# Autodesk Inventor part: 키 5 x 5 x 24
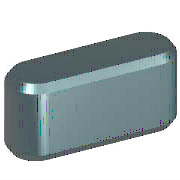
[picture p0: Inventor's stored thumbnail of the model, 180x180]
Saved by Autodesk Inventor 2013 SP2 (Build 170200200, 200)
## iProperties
IsCustomPart: 1
Created: 2012-02
Part Number: 키 5 x 5 x 24
Material: 강철, 연강
Description: 키 및 해당 키홈
Document SubType Name: Modeling
Standard: KS B 1311
Designer: mduedu
Standards Organization: KS
Language: ko-KR
Size Designation: 5 x 5 x 18
Categories: <MemberInstance><Categories><Category DisplayName="샤프트 부품" InternalName="7f7aeb1f-a693-4053-b835-cee3144e0d98" Mnemonic="SHFT"><Category DisplayName="키" Interna
Density: 1 g/cm^3
Author: mduedu
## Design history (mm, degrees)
workplane "Work Plane1"
workplane "Work Plane2"
sketch "스케치1"
  geometry: L1 (2.5, 2.5)-(21.5, 2.5); L2 (21.5, -2.5)-(2.5, -2.5); L3 (0, 8.9)-(0, -4.4) reference; L4 (-3.6, 0)-(21.6, 0) reference; L5 (24, 0)-(24, 7); A1 r 2.5 centre (2.5, 0) between (2.5, 2.5) and (2.5, -2.5); A2 r 2.5 centre (21.5, 0) between (21.5, -2.5) and (21.5, 2.5)
  constraints: 6 end point, 5 point on circle, 4 tangent, 3 point on line, 2 centre point, 1 horizontal, 1 parallel, 1 perpendicular
  dimensions: "d0" = 2.5 radius of A1 (= 0.5 x PB); "d13" = 2.5 radius of A2 (= 0.5 x PB); "d14" = 24 distance between parallel lines of L5 L3 (= NLG)
extrude "본체1" new body sketch "스케치1" taper "d3" = 0 deg; stored distance "d4" = 10
workplane "Work Plane3"
body "Solid1"
chamfer "모따기1" distance "d8" = 0.4 (= PHH); stored, may be unused: second distance "d9" = 0.4 (= PHH), angle "d15" = 45 deg
other parameters: "d1" = -3 (= -PNT), "d2" = 2 (= PH - PNT), "NLG" = 24 [user parameter; used in 3 equation terms], "PB" = 5 [user parameter; used in 2 equation terms], "PNT" = 3 [user parameter; used in 2 equation terms], "PH" = 5 [user parameter; used in 1 equation term], "PHH" = 0.4 [user parameter; used in 2 equation terms], "d10" = 0, "d16" = 0, "d17" = 0, "d18" = 0, "WDMIN" = 12 [user parameter], "PLB2" = 24 (= NLG) [user parameter], "WDMAX" = 17 [user parameter], "PLB1" = 24 (= NLG) [user parameter], "RR" = 0.16 [user parameter], "PUEB" = 2.3 [user parameter]
